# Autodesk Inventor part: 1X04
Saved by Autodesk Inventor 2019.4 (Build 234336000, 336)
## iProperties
Created: 2020-03
Part Number: 1X04
Material: Generic
Document SubType Name: Modeling
Designer: Administrator
Density: 1 g/cm^3
Appearance: Default
Title: 1X04
Author: Administrator
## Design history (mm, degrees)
feature "Body2"
body "Solid1"
